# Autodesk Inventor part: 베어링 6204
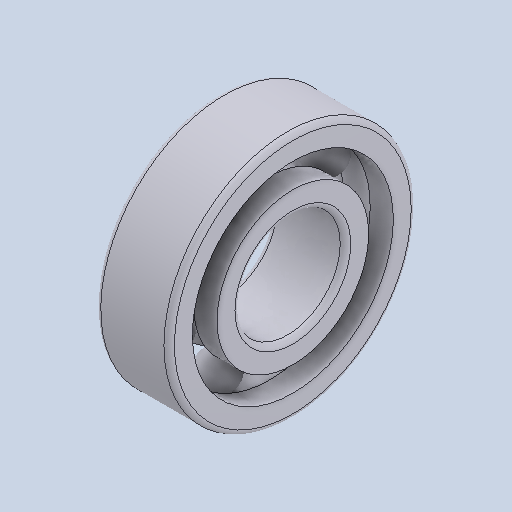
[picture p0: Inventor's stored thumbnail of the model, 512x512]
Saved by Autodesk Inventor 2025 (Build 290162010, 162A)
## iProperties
Created: 2024-08
Part Number: 베어링 6204
Material: 강철, 연강
Description: 깊은 그루브 볼 베어링
Document SubType Name: Modeling
Designer: 학생
Density: 7.86 g/cm^3
Appearance: 기본값
Author: jhkim
Sending System: Autodesk Inventor 2025
Preprocessor: ST-DEVELOPER v20
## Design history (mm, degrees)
feature "Solid1"
feature "Solid1:1"
feature "Solid1:2"
feature "Solid1:3"
feature "Solid1:4"
feature "Solid1:5"
feature "Solid1:6"
feature "Solid1:7"
feature "Solid1:8"
node "솔리드1"
node "솔리드2"
node "솔리드3"
node "솔리드4"
node "솔리드5"
node "솔리드6"
node "솔리드7"
node "솔리드8"
node "솔리드9"
